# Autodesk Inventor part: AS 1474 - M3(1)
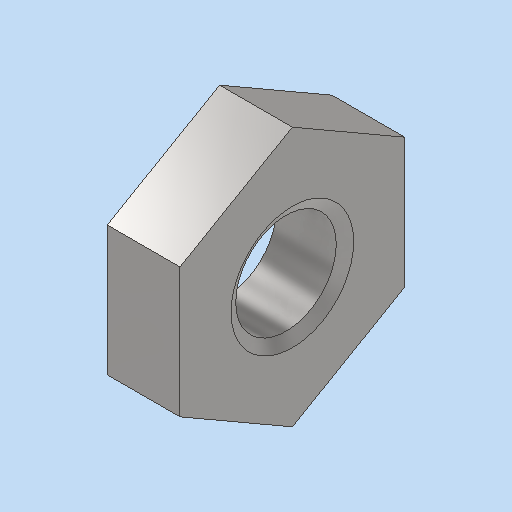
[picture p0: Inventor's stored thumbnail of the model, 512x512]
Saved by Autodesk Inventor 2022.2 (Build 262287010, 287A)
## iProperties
Created: 2024-01
Part Number: AS 1474 - M3(1)
Material: Acciaio, Dolce
Document SubType Name: Modeling
Designer: 18907419
Density: 7.85 g/cm^3
Appearance: Default
Author: 18907419
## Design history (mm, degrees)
feature "Solid1"
node "Solido1"
